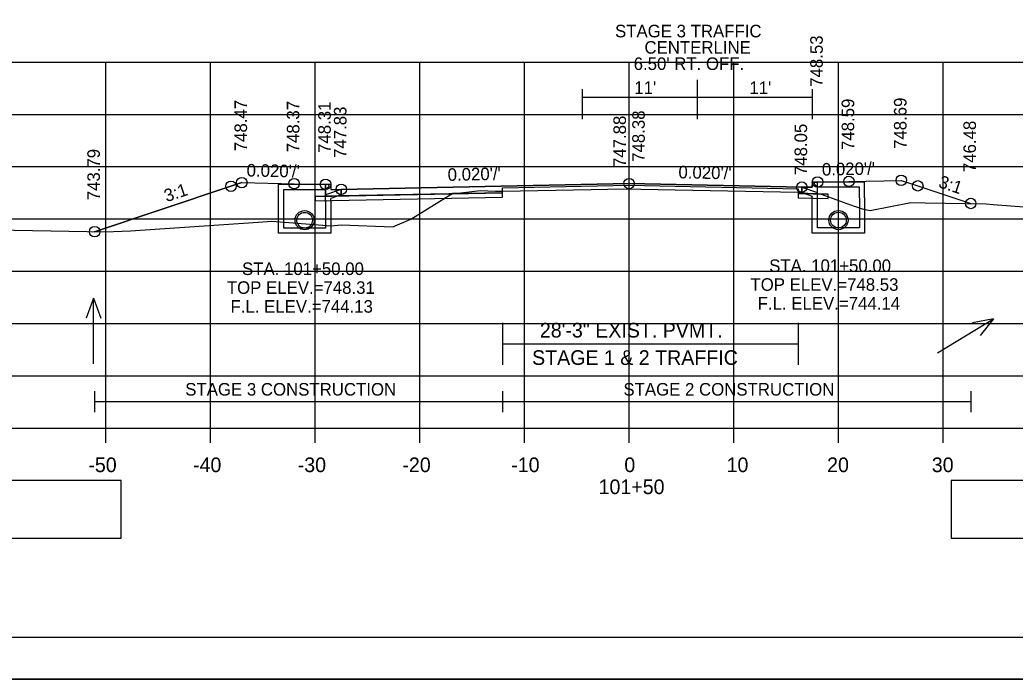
# Model space of a CAD drawing. Extents: x 1202951 to 1376887, y 378065 to 728038.
# Drawn here: x 1376526.5 to 1376621.5, y 378407.8 to 378470.8 of the extents above; entities that cross this region are included whole.
import ezdxf

# ---------------------------------------------------------------- set-up
doc = ezdxf.new("R2010")
doc.units = 0
for name, color, linetype in [('Default', 7, 'Continuous'), ('R_Alt Surface', 7, 'Continuous'), ('R_Axis', 7, 'Continuous'), ('R_Axis Annot', 7, 'Continuous'), ('R_Border', 7, 'Continuous'), ('R_Dimension', 7, 'Continuous'), ('R_Exist Surface', 7, 'Continuous'), ('R_Fin Surface', 7, 'Continuous'), ('R_Grid', 7, 'Continuous'), ('R_MOT', 7, 'Continuous'), ('R_No Plot', 7, 'Continuous'), ('R_Proposed Const Limits', 7, 'Continuous'), ('R_Water', 7, 'Continuous'), ('R_Water Annot', 7, 'Continuous'), ('R_Xsect Elev', 7, 'Continuous'), ('R_Xsect Slope', 7, 'Continuous')]:
    doc.layers.add(name, color=color, linetype=linetype)

msp = doc.modelspace()

# ---------------------------------------------------------------- linework, layer by layer
msp.add_circle((1376604.671, 378451.709), 0.917)
at = {"layer": 'Default'}
for points in [[(1376555.671, 378455.128), (1376556.161, 378455.128), (1376556.171, 378454.628), (1376557.171, 378454.648), (1376557.171, 378454.021), (1376555.671, 378453.991)], [(1376602.671, 378455.348), (1376602.181, 378455.348), (1376602.171, 378454.848), (1376601.171, 378454.868), (1376601.171, 378454.241), (1376602.671, 378454.211)]]:
    msp.add_lwpolyline(points, close=True, dxfattribs=at)
at = {"layer": 'R_Alt Surface'}
for p, q in [((1376554.671, 378453.971), (1376572.56, 378454.329)), ((1376600.819, 378454.248), (1376603.671, 378454.191)), ((1376603.671, 378454.142), (1376603.671, 378454.151))]:
    msp.add_line(p, q, dxfattribs=at)
msp.add_lwpolyline([(1376555.671, 378455.128), (1376555.671, 378453.991), (1376557.171, 378454.021), (1376572.56, 378454.329), (1376572.56, 378454.789), (1376584.671, 378455.031), (1376600.819, 378454.708), (1376600.819, 378454.248), (1376601.171, 378454.241), (1376602.671, 378454.211), (1376602.671, 378455.348)], dxfattribs=at)
for points in [[(1376557.171, 378454.648), (1376557.171, 378454.021), (1376572.56, 378454.329), (1376572.56, 378454.789), (1376584.671, 378455.031), (1376600.819, 378454.708), (1376600.819, 378454.248), (1376601.171, 378454.241), (1376601.171, 378454.868), (1376601.171, 378454.868), (1376584.671, 378455.198), (1376557.171, 378454.648)], [(1376557.171, 378454.021), (1376555.671, 378453.991), (1376554.671, 378453.971), (1376554.671, 378453.551), (1376572.56, 378453.909), (1376572.56, 378454.329)], [(1376603.671, 378454.191), (1376602.671, 378454.211), (1376601.171, 378454.241), (1376600.819, 378454.248), (1376600.819, 378453.828), (1376603.671, 378453.771)], [(1376434.671, 378421.294), (1376536.138, 378421.294), (1376536.138, 378426.817), (1376434.671, 378426.817)], [(1376615.432, 378421.294), (1376726.141, 378421.294), (1376726.141, 378426.817), (1376615.432, 378426.817)]]:
    msp.add_lwpolyline(points, close=True, dxfattribs=at)
at = {"layer": 'R_Axis'}
for p, q in [((1376434.671, 378431.817), (1376734.671, 378431.817)), ((1376534.671, 378430.417), (1376534.671, 378431.817)), ((1376544.671, 378430.417), (1376544.671, 378431.817)), ((1376554.671, 378430.417), (1376554.671, 378431.817)), ((1376564.671, 378430.417), (1376564.671, 378431.817)), ((1376574.671, 378430.417), (1376574.671, 378431.817)), ((1376584.671, 378430.417), (1376584.671, 378431.817)), ((1376594.671, 378430.417), (1376594.671, 378431.817)), ((1376604.671, 378430.417), (1376604.671, 378431.817)), ((1376614.671, 378430.417), (1376614.671, 378431.817))]:
    msp.add_line(p, q, dxfattribs=at)
at = {"layer": 'R_Border'}
msp.add_line((1376742.851, 378411.817), (1376426.671, 378411.817), dxfattribs=at)
at = {"layer": 'R_Dimension'}
for points in [[(1376533.615, 378435.356), (1376533.615, 378433.356)], [(1376572.56, 378435.356), (1376572.56, 378433.356)], [(1376617.305, 378435.356), (1376617.305, 378433.356)], [(1376533.615, 378434.356), (1376572.56, 378434.356)], [(1376572.56, 378434.356), (1376617.305, 378434.356)]]:
    msp.add_lwpolyline(points, dxfattribs=at)
at = {"layer": 'R_Exist Surface'}
msp.add_lwpolyline([(1376515.508, 378450.949), (1376534.634, 378450.583), (1376537.042, 378450.684), (1376549.237, 378451.526), (1376550.546, 378451.61), (1376556.205, 378451.171), (1376557.17, 378451.25), (1376562.087, 378451.051), (1376563.804, 378451.812), (1376567.816, 378454.278), (1376568.608, 378454.306), (1376570.457, 378454.548), (1376571.898, 378454.481), (1376572.56, 378454.472), (1376581.055, 378454.647), (1376584.155, 378454.709), (1376589.056, 378454.608), (1376600.819, 378454.366), (1376602.059, 378454.265), (1376603.002, 378454.171), (1376606.164, 378453.039), (1376606.307, 378452.995), (1376606.933, 378452.797), (1376607.705, 378452.611), (1376611.589, 378453.392), (1376612.941, 378453.367), (1376618.766, 378453.273), (1376619.443, 378453.208), (1376622.812, 378452.934)], dxfattribs=at)
msp.add_circle((1376553.671, 378451.697), 0.917, dxfattribs=at)
at = {"layer": 'R_Fin Surface'}
for p, q in [((1376572.56, 378441.887), (1376572.56, 378437.887)), ((1376600.819, 378441.887), (1376600.819, 378437.887)), ((1376572.56, 378439.887), (1376600.819, 378439.887))]:
    msp.add_line(p, q, dxfattribs=at)
for points in [[(1376533.615, 378450.602), (1376546.637, 378454.943), (1376547.671, 378455.288), (1376552.671, 378455.188), (1376555.671, 378455.128), (1376556.161, 378455.128), (1376556.171, 378454.628), (1376557.171, 378454.648), (1376584.671, 378455.198), (1376601.171, 378454.868), (1376602.171, 378454.848), (1376602.181, 378455.348), (1376602.671, 378455.348), (1376605.671, 378455.408), (1376610.671, 378455.508), (1376612.249, 378454.982), (1376617.305, 378453.296)], [(1376547.671, 378455.288), (1376552.671, 378455.188), (1376555.671, 378455.128), (1376556.161, 378455.128), (1376556.171, 378454.628), (1376557.171, 378454.648), (1376557.171, 378454.648), (1376584.671, 378455.198), (1376601.171, 378454.868), (1376601.171, 378454.868), (1376602.171, 378454.848), (1376602.181, 378455.348), (1376602.671, 378455.348), (1376605.671, 378455.408), (1376610.671, 378455.508)]]:
    msp.add_lwpolyline(points, dxfattribs=at)
at = {"layer": 'R_Grid'}
for p, q in [((1376434.671, 378466.817), (1376734.671, 378466.817)), ((1376534.671, 378431.817), (1376534.671, 378466.817)), ((1376544.671, 378431.817), (1376544.671, 378466.817)), ((1376554.671, 378431.817), (1376554.671, 378466.817)), ((1376564.671, 378431.817), (1376564.671, 378466.817)), ((1376574.671, 378431.817), (1376574.671, 378466.817)), ((1376584.671, 378431.817), (1376584.671, 378466.817)), ((1376594.671, 378431.817), (1376594.671, 378466.817)), ((1376604.671, 378431.817), (1376604.671, 378466.817)), ((1376614.671, 378431.817), (1376614.671, 378466.817)), ((1376434.671, 378461.817), (1376734.671, 378461.817)), ((1376434.671, 378456.817), (1376734.671, 378456.817)), ((1376434.671, 378451.817), (1376734.671, 378451.817)), ((1376434.671, 378446.817), (1376734.671, 378446.817)), ((1376434.671, 378441.817), (1376734.671, 378441.817)), ((1376434.671, 378436.817), (1376734.671, 378436.817)), ((1376434.671, 378431.817), (1376734.671, 378431.817))]:
    msp.add_line(p, q, dxfattribs=at)
at = {"layer": 'R_MOT'}
for p, q in [((1376591.171, 378465.122), (1376591.171, 378461.365)), ((1376580.171, 378464.211), (1376580.171, 378461.365)), ((1376602.171, 378464.211), (1376602.171, 378461.365)), ((1376580.171, 378463.461), (1376591.171, 378463.461)), ((1376591.171, 378463.461), (1376602.171, 378463.461))]:
    msp.add_line(p, q, dxfattribs=at)
at = {"layer": 'R_No Plot'}
msp.add_line((1376414.27, 378407.838), (1376747.604, 378407.838), dxfattribs=at)
for points in [[(1376414.264, 378621.171), (1376747.604, 378621.171), (1376747.604, 378407.834), (1376414.264, 378407.834)], [(1376660.591, 378617.277), (1376680.211, 378617.277), (1376680.211, 378607.397), (1376696.323, 378607.397), (1376719.523, 378607.397), (1376719.643, 378579.24), (1376742.851, 378579.24), (1376742.851, 378411.817), (1376426.671, 378411.817), (1376426.671, 378617.277)]]:
    msp.add_lwpolyline(points, close=True, dxfattribs=at)
for centre in [(1376546.637, 378454.943), (1376547.671, 378455.288), (1376547.671, 378455.288), (1376552.671, 378455.188), (1376552.671, 378455.188), (1376555.671, 378455.128), (1376555.671, 378455.128), (1376584.671, 378455.198), (1376584.671, 378455.198), (1376602.671, 378455.348), (1376602.671, 378455.348), (1376605.671, 378455.408), (1376605.671, 378455.408), (1376610.671, 378455.508), (1376610.671, 378455.508), (1376612.249, 378454.982), (1376557.171, 378454.648), (1376557.171, 378454.648), (1376601.171, 378454.868), (1376601.171, 378454.868), (1376617.305, 378453.296), (1376617.305, 378453.296), (1376533.615, 378450.602), (1376533.615, 378450.602)]:
    msp.add_circle(centre, 0.5, dxfattribs=at)
at = {"layer": 'R_Proposed Const Limits'}
for points in [[(1376610.671, 378455.508), (1376612.249, 378454.982), (1376612.249, 378454.982), (1376617.305, 378453.296)], [(1376547.671, 378455.288), (1376546.637, 378454.943), (1376546.637, 378454.943), (1376533.615, 378450.602)]]:
    msp.add_lwpolyline(points, dxfattribs=at)
at = {"layer": 'R_Water'}
for p, q in [((1376551.171, 378455.127), (1376555.921, 378455.127)), ((1376551.171, 378453.627), (1376551.171, 378455.127)), ((1376551.671, 378453.627), (1376551.671, 378454.627)), ((1376551.671, 378454.627), (1376555.671, 378454.627)), ((1376556.004, 378454.961), (1376555.671, 378454.627)), ((1376557.171, 378454.647), (1376555.671, 378454.127)), ((1376556.004, 378454.961), (1376555.921, 378455.127)), ((1376601.171, 378454.867), (1376602.671, 378454.347)), ((1376602.338, 378455.181), (1376602.421, 378455.347)), ((1376602.338, 378455.181), (1376602.671, 378454.847)), ((1376607.171, 378455.347), (1376602.421, 378455.347)), ((1376606.671, 378454.847), (1376602.671, 378454.847)), ((1376606.671, 378453.847), (1376606.671, 378454.847)), ((1376607.171, 378453.847), (1376607.171, 378455.347)), ((1376555.671, 378453.627), (1376555.671, 378454.127)), ((1376557.171, 378454.117), (1376556.171, 378453.771)), ((1376556.171, 378453.627), (1376556.171, 378453.771)), ((1376601.171, 378454.337), (1376602.171, 378453.991)), ((1376602.171, 378453.847), (1376602.171, 378453.991)), ((1376602.671, 378453.847), (1376602.671, 378454.347))]:
    msp.add_line(p, q, dxfattribs=at)
for points in [[(1376557.171, 378454.117), (1376557.171, 378454.647)], [(1376601.171, 378454.337), (1376601.171, 378454.867)], [(1376556.171, 378453.627), (1376556.171, 378450.447), (1376553.671, 378450.447), (1376551.171, 378450.447), (1376551.171, 378453.627)], [(1376555.671, 378453.627), (1376555.671, 378450.947), (1376553.671, 378450.947), (1376551.671, 378450.947), (1376551.671, 378453.627)], [(1376607.171, 378453.847), (1376607.171, 378450.459), (1376604.671, 378450.459), (1376602.171, 378450.459), (1376602.171, 378453.847)], [(1376606.671, 378453.847), (1376606.671, 378450.959), (1376604.671, 378450.959), (1376602.671, 378450.959), (1376602.671, 378453.847)]]:
    msp.add_lwpolyline(points, dxfattribs=at)
for centre in [(1376553.671, 378451.697), (1376604.671, 378451.709)]:
    msp.add_circle(centre, 0.75, dxfattribs=at)
at = {"layer": 'R_Water Annot'}
for p, q in [((1376533.508, 378444.251), (1376532.808, 378442.328)), ((1376533.508, 378437.967), (1376533.508, 378444.251)), ((1376533.508, 378444.251), (1376534.208, 378442.328)), ((1376614.13, 378439.006), (1376619.491, 378442.285)), ((1376619.491, 378442.285), (1376617.485, 378441.879)), ((1376619.491, 378442.285), (1376618.216, 378440.684))]:
    msp.add_line(p, q, dxfattribs=at)
at = {"layer": 'R_Xsect Elev'}
msp.add_line((1376584.671, 378454.698), (1376584.671, 378463.052), dxfattribs=at)

# ---------------------------------------------------------------- texts
at = {"layer": 'R_Axis Annot'}
for s, p in [('28\'-3" EXIST. PVMT.', (1376576.145, 378440.485)), ('STAGE 1 & 2 TRAFFIC', (1376575.4, 378437.868)), ('-50', (1376533.012, 378427.617)), ('-40', (1376543.012, 378427.617)), ('-30', (1376553.012, 378427.617)), ('-20', (1376563.012, 378427.617)), ('-10', (1376573.409, 378427.617)), ('0', (1376584.214, 378427.617)), ('10', (1376593.982, 378427.617)), ('20', (1376603.585, 378427.617)), ('30', (1376613.585, 378427.617)), ('101+50', (1376581.755, 378425.517))]:
    msp.add_text(s, height=1.4, dxfattribs=at).set_placement(p)
at = {"layer": 'R_Dimension'}
for s, p in [('STAGE 3 CONSTRUCTION', (1376542.269, 378434.934)), ('STAGE 2 CONSTRUCTION', (1376584.126, 378434.934))]:
    msp.add_text(s, height=1.2, dxfattribs=at).set_placement(p)
at = {"layer": 'R_MOT'}
for s, p in [('STAGE 3 TRAFFIC ', (1376583.324, 378469.176)), ('CENTERLINE', (1376586.135, 378467.616)), ("6.50' RT. OFF.", (1376585.105, 378466.056)), ("11'", (1376585.163, 378463.767)), ("11'", (1376596.163, 378463.767))]:
    msp.add_text(s, height=1.2, dxfattribs=at).set_placement(p)
at = {"layer": 'R_Water Annot'}
for s, p in [('STA. 101+50.00', (1376598.052, 378446.75)), ('STA. 101+50.00', (1376547.691, 378446.458)), ('TOP ELEV.=748.31', (1376546.241, 378444.658)), ('TOP ELEV.=748.53', (1376596.262, 378444.95)), ('F.L. ELEV.=744.13', (1376546.59, 378442.858)), ('F.L. ELEV.=744.14', (1376596.952, 378443.15))]:
    msp.add_text(s, height=1.2, dxfattribs=at).set_placement(p)
at = {"layer": 'R_Xsect Elev'}
for s, p in [('748.53', (1376603.171, 378464.451)), ('748.47', (1376548.171, 378458.288)), ('748.47', (1376548.171, 378458.288)), ('748.37', (1376553.171, 378458.188)), ('748.37', (1376553.171, 378458.188)), ('748.59', (1376606.171, 378458.408)), ('748.59', (1376606.171, 378458.408)), ('748.69', (1376611.171, 378458.508)), ('748.69', (1376611.171, 378458.508)), ('748.31', (1376556.171, 378458.128)), ('748.31', (1376556.171, 378458.128)), ('747.83', (1376557.671, 378457.648)), ('747.83', (1376557.671, 378457.648)), ('748.38', (1376586.167, 378457.279)), ('747.88', (1376584.371, 378456.78)), ('746.48', (1376617.805, 378456.296)), ('746.48', (1376617.805, 378456.296)), ('748.05', (1376601.671, 378456.01)), ('743.79', (1376534.115, 378453.602)), ('743.79', (1376534.115, 378453.602))]:
    msp.add_text(s, height=1.2, rotation=90, dxfattribs=at).set_placement(p)
at = {"layer": 'R_Xsect Slope'}
for s, rotation, p in [("0.020'/'", 1.14576, (1376603.098, 378455.956)), ("0.020'/'", 358.85424, (1376548.122, 378455.879)), ("0.020'/'", 1.14576, (1376567.348, 378455.451)), ("0.020'/'", 358.85424, (1376589.372, 378455.704)), ('3:1', 341.56505, (1376614.146, 378454.876)), ('3:1', 18.43495, (1376540.485, 378453.419))]:
    msp.add_text(s, height=1.2, rotation=rotation, dxfattribs=at).set_placement(p)

doc.saveas('drawing.dxf')
